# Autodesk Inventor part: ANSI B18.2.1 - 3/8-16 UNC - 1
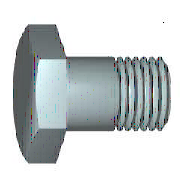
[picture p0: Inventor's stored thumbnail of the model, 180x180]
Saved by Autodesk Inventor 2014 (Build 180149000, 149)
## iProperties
IsCustomPart: 0
Created: 2008-02
Part Number: ANSI B18.2.1 - 3/8-16 UNC - 1
Material: Steel, Mild
Description: Hex Cap Screw
Document SubType Name: Modeling
Standard: ANSI B18.2.1
Designer: floress
Standard Revision: 1996
Standards Organization: ANSI
Language: en-US
Size Designation: 3/8-16 UNC - 1
Categories: <MemberInstance><Categories><Category DisplayName="Fasteners" InternalName="e4da775c-781d-43d5-af7c-5136215cf5a6" Mnemonic="FSTN"><Category DisplayName="Bolts"
Density: 7.86 g/cm^3
Mass: 22.109 g
Surface Area: 13.6448 cm^2
Volume: 2.81285 cm^3
Appearance: Steel
Author: floress
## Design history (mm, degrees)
sketch "Sketch1"
  geometry: L1 (0, 6.429)-(0, 4.762); L2 (3.962, 4.762)-(25.4, 4.763); L3 (25.4, 4.763)-(25.4, 0); L4 (25.4, 0)-(-0.635, 0); L5 (-5.842, 0)-(30.607, 0) reference; L6 (-0.635, 0)-(-0.635, 6.429); L7 (-0.635, 6.429)-(0, 6.429); L8 (3.962, 4.762)-(2.375, 4.762); L9 (2.375, 4.762)-(0, 4.762); L10 (0, -1.286)-(0, 7.715) reference
  constraints: 16 end point, 2 collinear, 2 perpendicular, 1 parallel
  dimensions: "d0" = 25.4 distance between parallel lines of L3 L1 (= NLG); "d1" = 21.4376 distance from line of L2.start L3 (= GEL); "d2" = 9.525 diameter of L2 L4 (= GD); "d9" = 0.6351 distance between parallel lines of L6 L1 (computed from SD); "d10" = 12.85875 diameter of L7 L4 (= SD2); "d13" = 1.5876 distance of L2.start L8.end (computed from GAL); "d14" = 9.525 diameter of L9 L4 (= BDM)
revolve "Body" sketch "Sketch1" stored, may be unused: angle "d12" = 90 deg
sketch "Sketch2"
  geometry: L1 (0, 8.249)-(7.144, 4.124); L2 (7.144, 4.124)-(7.144, -4.124); L3 (7.144, -4.124)-(0, -8.249); L4 (0, -8.249)-(-7.144, -4.124); L5 (-7.144, -4.124)-(-7.144, 4.124); L6 (-7.144, 4.124)-(0, 8.249); 2 further points
  constraints: 12 end point, 1 coincident, 1 vertical, 11 other
  dimensions: "d11" = 14.2875 distance between parallel lines of L5 L2 (= SW)
extrude "Head" join sketch "Sketch2" distance "d3" = 5.31813 (= KOH - SD); taper "d4" = 0 deg
sketch "Sketch4"
  geometry: L1 (-5.953, 7.144)-(-5.953, 8.249); L2 (-5.953, 8.249)-(-5.315, 8.249); L3 (-5.315, 8.249)-(-5.953, 7.144); L4 (-7.017, 0)-(0.429, 0) reference; L5 (-0.635, 8.249)-(-5.953, 8.249) reference; L6 (-5.953, 4.124)-(-5.953, 8.249) reference
  constraints: 6 end point, 2 collinear, 1 perpendicular, 1 vertical
  dimensions: "d5" = 30 deg angle of L3 L1 (= ANG1); "d19" = 14.2875 diameter of L1.start L4 (= SW0)
revolve "Chamfer1" sketch "Sketch4" stored, may be unused: angle "d21" = 90 deg
workplane "Work Plane1"
fillet "Fillet2" dims "d63" = 0.635 (= R)
body "Solid1"
feature "Thread" dims "d15" = 21.4376 (= GEL), "d16" = 0
chamfer "Chamfer2" distance "d6" = 0.85928 (= -0.5 x SPD + 0.5 x GD); stored, may be unused: second distance "d7" = 1.5876 (computed from GUL), angle "d55" = 45 deg
other parameters: "NLG" = 25.4 [user parameter; used in 2 equation terms], "GD" = 9.525 (= NND) [user parameter; used in 2 equation terms], "BDM" = 9.525 [user parameter; used in 1 equation term], "KOH" = 5.95312 [user parameter; used in 1 equation term], "GEL" = 21.4376 [user parameter; used in 2 equation terms], "SW" = 14.2875 [user parameter; used in 3 equation terms], "SW0" = 14.2875 (= SW) [user parameter; used in 1 equation term], "SPD" = 7.80644 (= GD1) [user parameter; used in 1 equation term], "SD2" = 12.85875 [user parameter; used in 1 equation term], "SD" = 0.635 [user parameter; used in 3 equation terms], "ANG1" = 30 deg [user parameter; used in 1 equation term], "GAL" = 1.5875 [user parameter; used in 1 equation term], "GUL" = 1.5875 [user parameter; used in 2 equation terms], "d8" = 0, "R" = 0.635 [user parameter; used in 1 equation term], "d58" = 0, "d62" = -24.4475 (= -NLG - SD + GUL), "THREADDIA" = 9.525 [user parameter], "TOA" = 30 deg [user parameter], "RR" = 0.508 [user parameter], "PTC" = 1.5875 (computed from TPU) [user parameter], "NND" = 9.525 [user parameter; used in 1 equation term], "E0" = 16.50206 (= 1.155 x SW) [user parameter], "SLG" = 0 [user parameter], "GD1" = 7.80644 [user parameter; used in 1 equation term]
